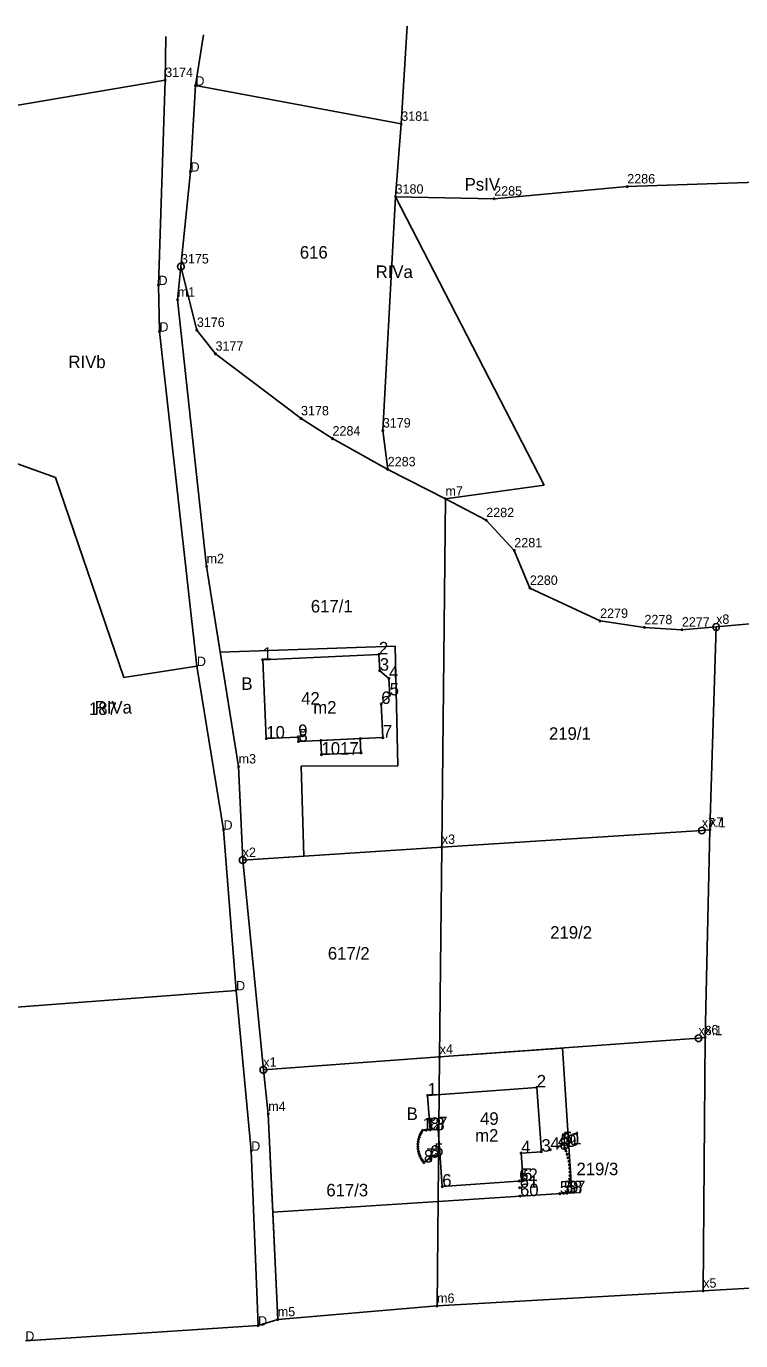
# Model space of a CAD drawing. Extents: x 7467189 to 7469366, y 5491487 to 5492734.
# Drawn here: x 7468649.2 to 7468735, y 5491668.5 to 5491826.2 of the extents above; entities that cross this region are included whole.
import ezdxf

# ---------------------------------------------------------------- set-up
doc = ezdxf.new("R2010")
doc.units = 0
for name, color, linetype in [('202-punkt graniczny', 7, 'Continuous'), ('202-punkt graniczny-Atr103', 7, 'Continuous'), ('203-punkt graniczny', 7, 'Continuous'), ('203-punkt graniczny-Atr103', 7, 'Continuous'), ('209-oznaczenie konturu klasyfikacyjnego', 7, 'Continuous'), ('210-oznaczenie konturu użytku gruntowego', 7, 'Continuous'), ('211-numer działki ewidencyjnej', 7, 'Continuous'), ('217-kontur klasyfikacyjny', 7, 'Continuous'), ('218-kontur użytku gruntowego', 7, 'Continuous'), ('219-działka ewidencyjna', 7, 'Continuous'), ('312-budynek ewidencyjny', 7, 'Continuous'), ('312-oznaczenie budynku ewidencyjnego', 7, 'Continuous'), ('312-oznaczenie budynku ewidencyjnego-Atr117', 7, 'Continuous'), ('352-schody', 7, 'Continuous'), ('Punkt budynku', 7, 'Continuous'), ('Punkt budynku-Atr104', 7, 'Continuous')]:
    doc.layers.add(name, color=color, linetype=linetype)

# ---------------------------------------------------------------- blocks, each defined once
blk = doc.blocks.new('203')
blk.add_circle((0, 0), 0.09)
blk = doc.blocks.new('202')
blk.add_circle((0, 0), 0.4)
blk = doc.blocks.new('PUNKTBUD')
blk.add_circle((0, 0), 0.09)

msp = doc.modelspace()

# ---------------------------------------------------------------- linework, layer by layer
at = {"layer": '217-kontur klasyfikacyjny'}
for points in [[(7468665.89, 5491819.71), (7468665.98, 5491824.92)], [(7468670.5, 5491825.12), (7468669.52, 5491819.04)], [(7468665.89, 5491819.71), (7468639.02, 5491815.12)], [(7468665.09, 5491795.12), (7468665.89, 5491819.71)], [(7468669.52, 5491819.04), (7468668.93, 5491808.73)], [(7468694.22, 5491814.44), (7468669.52, 5491819.04)], [(7468693.54, 5491805.71), (7468694.22, 5491814.44)], [(7468668.93, 5491808.73), (7468667.78, 5491797.33)], [(7468721.34, 5491806.93), (7468741.79, 5491807.63)], [(7468705.38, 5491805.47), (7468721.34, 5491806.93)], [(7468711.38, 5491771.14), (7468693.54, 5491805.71)], [(7468693.54, 5491805.71), (7468705.38, 5491805.47)], [(7468667.78, 5491797.33), (7468667.38, 5491793.36)], [(7468667.78, 5491797.33), (7468669.69, 5491789.73)], [(7468665.2, 5491789.55), (7468665.09, 5491795.12)], [(7468667.38, 5491793.36), (7468670.86, 5491761.39)], [(7468669.7, 5491749.44), (7468665.2, 5491789.55)], [(7468669.69, 5491789.73), (7468671.93, 5491786.88)], [(7468671.93, 5491786.88), (7468682.19, 5491779.12)], [(7468682.19, 5491779.12), (7468685.97, 5491776.71)], [(7468652.73, 5491772.06), (7468638.46, 5491777.15)], [(7468685.97, 5491776.71), (7468692.6, 5491773.01)], [(7468692.6, 5491773.01), (7468699.53, 5491769.49)], [(7468660.93, 5491748.06), (7468652.73, 5491772.06)], [(7468699.53, 5491769.49), (7468711.38, 5491771.14)], [(7468699.53, 5491769.49), (7468704.42, 5491766.92)], [(7468704.42, 5491766.92), (7468707.79, 5491763.3)], [(7468707.79, 5491763.3), (7468709.66, 5491758.79)], [(7468670.86, 5491761.39), (7468672.5, 5491751.11)], [(7468709.66, 5491758.79), (7468718.09, 5491754.84)], [(7468718.09, 5491754.84), (7468723.41, 5491754.07)], [(7468723.41, 5491754.07), (7468727.9, 5491753.79)], [(7468727.9, 5491753.79), (7468732.01, 5491754.12)], [(7468732.01, 5491754.12), (7468737.87, 5491754.64)], [(7468672.5, 5491751.11), (7468693.48, 5491751.8)], [(7468693.48, 5491751.8), (7468693.83, 5491737.45)], [(7468669.7, 5491749.44), (7468660.93, 5491748.06)], [(7468672.9, 5491729.81), (7468669.7, 5491749.44)], [(7468693.83, 5491737.45), (7468682.22, 5491737.44)], [(7468682.22, 5491737.44), (7468682.52, 5491726.65)], [(7468674.4, 5491710.54), (7468672.9, 5491729.81)], [(7468682.52, 5491726.65), (7468675.19, 5491726.17)], [(7468675.19, 5491726.17), (7468677.67, 5491701)], [(7468645.39, 5491708.33), (7468674.4, 5491710.54)], [(7468676.22, 5491691.31), (7468674.4, 5491710.54)], [(7468698.83, 5491702.56), (7468713.57, 5491703.62)], [(7468713.57, 5491703.62), (7468714.69, 5491686.26)], [(7468677.67, 5491701), (7468698.83, 5491702.56)], [(7468677.04, 5491670.34), (7468676.22, 5491691.31)], [(7468714.69, 5491686.26), (7468698.65, 5491685.23)], [(7468698.65, 5491685.23), (7468678.8, 5491683.96)], [(7468678.8, 5491683.96), (7468679.4, 5491671.07)], [(7468730.46, 5491674.51), (7468769.6, 5491676.74)], [(7468698.52, 5491672.7), (7468730.46, 5491674.51)], [(7468679.4, 5491671.07), (7468698.52, 5491672.7)], [(7468649.11, 5491668.53), (7468677.04, 5491670.34)]]:
    msp.add_lwpolyline(points, dxfattribs=at)
at = {"layer": '218-kontur użytku gruntowego'}
for points in [[(7468665.98, 5491824.92), (7468665.89, 5491819.71)], [(7468670.5, 5491825.12), (7468669.52, 5491819.04)], [(7468665.89, 5491819.71), (7468665.09, 5491795.12)], [(7468669.52, 5491819.04), (7468668.93, 5491808.73)], [(7468694.22, 5491814.44), (7468669.52, 5491819.04)], [(7468693.54, 5491805.71), (7468694.22, 5491814.44)], [(7468668.93, 5491808.73), (7468667.78, 5491797.33)], [(7468741.79, 5491807.63), (7468721.34, 5491806.93)], [(7468721.34, 5491806.93), (7468705.38, 5491805.47)], [(7468705.38, 5491805.47), (7468693.54, 5491805.71)], [(7468667.78, 5491797.33), (7468667.38, 5491793.36)], [(7468665.09, 5491795.12), (7468665.2, 5491789.55)], [(7468667.38, 5491793.36), (7468670.86, 5491761.39)], [(7468665.2, 5491789.55), (7468669.7, 5491749.44)], [(7468670.86, 5491761.39), (7468672.5, 5491751.11)], [(7468693.48, 5491751.8), (7468672.5, 5491751.11)], [(7468672.5, 5491751.11), (7468674.7, 5491737.38)], [(7468693.83, 5491737.45), (7468693.48, 5491751.8)], [(7468669.7, 5491749.44), (7468672.9, 5491729.81)], [(7468674.7, 5491737.38), (7468675.19, 5491726.17)], [(7468682.22, 5491737.44), (7468693.83, 5491737.45)], [(7468682.52, 5491726.65), (7468682.22, 5491737.44)], [(7468672.9, 5491729.81), (7468674.4, 5491710.54)], [(7468675.19, 5491726.17), (7468682.52, 5491726.65)], [(7468675.19, 5491726.17), (7468677.67, 5491701)], [(7468674.4, 5491710.54), (7468676.22, 5491691.31)], [(7468713.57, 5491703.62), (7468698.83, 5491702.56)], [(7468714.69, 5491686.26), (7468713.57, 5491703.62)], [(7468698.83, 5491702.56), (7468677.67, 5491701)], [(7468677.67, 5491701), (7468678.26, 5491695.71)], [(7468678.26, 5491695.71), (7468678.8, 5491683.96)], [(7468676.22, 5491691.31), (7468677.04, 5491670.34)], [(7468698.65, 5491685.23), (7468714.69, 5491686.26)], [(7468678.8, 5491683.96), (7468698.65, 5491685.23)], [(7468678.8, 5491683.96), (7468679.4, 5491671.07)], [(7468730.46, 5491674.51), (7468769.6, 5491676.74)], [(7468698.52, 5491672.7), (7468730.46, 5491674.51)], [(7468679.4, 5491671.07), (7468698.52, 5491672.7)], [(7468677.04, 5491670.34), (7468649.11, 5491668.53)]]:
    msp.add_lwpolyline(points, dxfattribs=at)
at = {"layer": '219-działka ewidencyjna'}
for points in [[(7468665.98, 5491824.92), (7468665.89, 5491819.71)], [(7468669.52, 5491819.04), (7468670.5, 5491825.12)], [(7468694.22, 5491814.44), (7468694.94, 5491826.16)], [(7468639.02, 5491815.12), (7468665.89, 5491819.71)], [(7468665.09, 5491795.12), (7468665.89, 5491819.71)], [(7468668.93, 5491808.73), (7468669.52, 5491819.04)], [(7468669.52, 5491819.04), (7468694.22, 5491814.44)], [(7468693.54, 5491805.71), (7468694.22, 5491814.44)], [(7468668.93, 5491808.73), (7468667.78, 5491797.33)], [(7468721.34, 5491806.93), (7468741.79, 5491807.63)], [(7468705.38, 5491805.47), (7468721.34, 5491806.93)], [(7468692.01, 5491777.67), (7468693.54, 5491805.71)], [(7468693.54, 5491805.71), (7468705.38, 5491805.47)], [(7468667.38, 5491793.36), (7468667.78, 5491797.33)], [(7468667.78, 5491797.33), (7468669.69, 5491789.73)], [(7468665.09, 5491795.12), (7468665.2, 5491789.55)], [(7468667.38, 5491793.36), (7468670.86, 5491761.39)], [(7468665.2, 5491789.55), (7468669.7, 5491749.44)], [(7468669.69, 5491789.73), (7468671.93, 5491786.88)], [(7468671.93, 5491786.88), (7468682.19, 5491779.12)], [(7468682.19, 5491779.12), (7468685.97, 5491776.71)], [(7468692.01, 5491777.67), (7468692.6, 5491773.01)], [(7468685.97, 5491776.71), (7468692.6, 5491773.01)], [(7468699.53, 5491769.49), (7468692.6, 5491773.01)], [(7468699.09, 5491727.73), (7468699.53, 5491769.49)], [(7468699.53, 5491769.49), (7468704.42, 5491766.92)], [(7468704.42, 5491766.92), (7468707.79, 5491763.3)], [(7468707.79, 5491763.3), (7468709.66, 5491758.79)], [(7468670.86, 5491761.39), (7468674.7, 5491737.38)], [(7468709.66, 5491758.79), (7468718.09, 5491754.84)], [(7468718.09, 5491754.84), (7468723.41, 5491754.07)], [(7468723.41, 5491754.07), (7468727.9, 5491753.79)], [(7468732.01, 5491754.12), (7468727.9, 5491753.79)], [(7468731.27, 5491729.81), (7468732.01, 5491754.12)], [(7468732.01, 5491754.12), (7468737.87, 5491754.64)], [(7468669.7, 5491749.44), (7468672.9, 5491729.81)], [(7468674.7, 5491737.38), (7468675.19, 5491726.17)], [(7468672.9, 5491729.81), (7468674.4, 5491710.54)], [(7468699.09, 5491727.73), (7468730.3, 5491729.72)], [(7468730.3, 5491729.72), (7468731.27, 5491729.81)], [(7468730.69, 5491704.89), (7468731.27, 5491729.81)], [(7468675.19, 5491726.17), (7468699.09, 5491727.73)], [(7468698.83, 5491702.56), (7468699.09, 5491727.73)], [(7468675.19, 5491726.17), (7468677.67, 5491701)], [(7468674.4, 5491710.54), (7468676.22, 5491691.31)], [(7468698.83, 5491702.56), (7468729.89, 5491704.8)], [(7468729.89, 5491704.8), (7468730.69, 5491704.89)], [(7468730.46, 5491674.51), (7468730.69, 5491704.89)], [(7468677.67, 5491701), (7468698.83, 5491702.56)], [(7468698.52, 5491672.7), (7468698.83, 5491702.56)], [(7468677.67, 5491701), (7468678.26, 5491695.71)], [(7468678.26, 5491695.71), (7468679.4, 5491671.07)], [(7468676.22, 5491691.31), (7468677.04, 5491670.34)], [(7468730.46, 5491674.51), (7468769.6, 5491676.74)], [(7468698.52, 5491672.7), (7468730.46, 5491674.51)], [(7468679.4, 5491671.07), (7468698.52, 5491672.7)], [(7468677.04, 5491670.34), (7468679.4, 5491671.07)], [(7468649.11, 5491668.53), (7468677.04, 5491670.34)]]:
    msp.add_lwpolyline(points, dxfattribs=at)
at = {"layer": '312-budynek ewidencyjny'}
for points in [[(7468677.59, 5491750.19), (7468691.54, 5491750.83)], [(7468691.54, 5491750.83), (7468691.64, 5491748.88)], [(7468678.02, 5491740.74), (7468677.59, 5491750.19)], [(7468691.64, 5491748.88), (7468692.75, 5491747.95)], [(7468692.75, 5491747.95), (7468692.84, 5491745.92)], [(7468692.84, 5491745.92), (7468691.82, 5491744.89)], [(7468691.82, 5491744.89), (7468692.01, 5491740.85)], [(7468681.85, 5491740.92), (7468678.02, 5491740.74)], [(7468681.88, 5491740.39), (7468681.85, 5491740.92)], [(7468692.01, 5491740.85), (7468681.88, 5491740.39)], [(7468697.38, 5491697.94), (7468710.48, 5491698.9)], [(7468710.48, 5491698.9), (7468711.04, 5491691.2)], [(7468697.68, 5491693.82), (7468697.38, 5491697.94)], [(7468698.64, 5491693.88), (7468697.68, 5491693.82)], [(7468699.14, 5491687.01), (7468698.64, 5491693.88)], [(7468711.04, 5491691.2), (7468708.61, 5491691.02)], [(7468708.61, 5491691.02), (7468708.85, 5491687.72)], [(7468708.85, 5491687.72), (7468699.14, 5491687.01)]]:
    msp.add_lwpolyline(points, dxfattribs=at)
at = {"layer": '352-schody'}
for points in [[(7468689.31, 5491740.73), (7468689.39, 5491739.03), (7468684.65, 5491738.81), (7468684.57, 5491740.51)], [(7468689.31, 5491740.73), (7468689.39, 5491739.03), (7468684.65, 5491738.81), (7468684.57, 5491740.51)], [(7468697.68, 5491693.82), (7468698.64, 5491693.88), (7468698.86, 5491690.79), (7468698.18, 5491690.7), (7468697.67, 5491690.47), (7468697.22, 5491690.11), (7468696.93, 5491689.9), (7468696.76, 5491690.14), (7468696.6, 5491690.39), (7468696.48, 5491690.66), (7468696.37, 5491690.93), (7468696.29, 5491691.22), (7468696.24, 5491691.51), (7468696.22, 5491691.8), (7468696.22, 5491692.1), (7468696.25, 5491692.39), (7468696.3, 5491692.68), (7468696.39, 5491692.96), (7468696.49, 5491693.24), (7468696.63, 5491693.5), (7468696.78, 5491693.75), (7468697.2, 5491693.78)], [(7468697.68, 5491693.82), (7468698.64, 5491693.88), (7468698.86, 5491690.79), (7468698.18, 5491690.7), (7468697.67, 5491690.47), (7468697.22, 5491690.11), (7468696.93, 5491689.9), (7468696.76, 5491690.14), (7468696.6, 5491690.39), (7468696.48, 5491690.66), (7468696.37, 5491690.93), (7468696.29, 5491691.22), (7468696.24, 5491691.51), (7468696.22, 5491691.8), (7468696.22, 5491692.1), (7468696.25, 5491692.39), (7468696.3, 5491692.68), (7468696.39, 5491692.96), (7468696.49, 5491693.24), (7468696.63, 5491693.5), (7468696.78, 5491693.75), (7468697.2, 5491693.78)]]:
    msp.add_lwpolyline(points, close=True, dxfattribs=at)

# ---------------------------------------------------------------- block references
at = {"layer": '202-punkt graniczny'}
for p in [(7468667.78, 5491797.33), (7468732.01, 5491754.12), (7468730.3, 5491729.72), (7468675.19, 5491726.17), (7468729.89, 5491704.8), (7468677.67, 5491701)]:
    msp.add_blockref('202', p, dxfattribs=at)
at = {"layer": '203-punkt graniczny'}
for p in [(7468665.89, 5491819.71), (7468669.52, 5491819.04), (7468694.22, 5491814.44), (7468668.93, 5491808.73), (7468721.34, 5491806.93), (7468693.54, 5491805.71), (7468705.38, 5491805.47), (7468665.09, 5491795.12), (7468667.38, 5491793.36), (7468665.2, 5491789.55), (7468669.69, 5491789.73), (7468671.93, 5491786.88), (7468682.19, 5491779.12), (7468692.01, 5491777.67), (7468685.97, 5491776.71), (7468692.6, 5491773.01), (7468699.53, 5491769.49), (7468704.42, 5491766.92), (7468707.79, 5491763.3), (7468670.86, 5491761.39), (7468709.66, 5491758.79), (7468718.09, 5491754.84), (7468723.41, 5491754.07), (7468727.9, 5491753.79), (7468669.7, 5491749.44), (7468674.7, 5491737.38), (7468672.9, 5491729.81), (7468731.27, 5491729.81), (7468699.09, 5491727.73), (7468674.4, 5491710.54), (7468730.69, 5491704.89), (7468698.83, 5491702.56), (7468678.26, 5491695.71), (7468676.22, 5491691.31), (7468730.46, 5491674.51), (7468698.52, 5491672.7), (7468677.04, 5491670.34), (7468679.4, 5491671.07)]:
    msp.add_blockref('203', p, dxfattribs=at)
at = {"layer": 'Punkt budynku'}
for p in [(7468691.54, 5491750.83), (7468677.59, 5491750.19), (7468691.64, 5491748.88), (7468692.75, 5491747.95), (7468691.82, 5491744.89), (7468692.84, 5491745.92), (7468678.02, 5491740.74), (7468681.85, 5491740.92), (7468681.88, 5491740.39), (7468684.57, 5491740.51), (7468689.31, 5491740.73), (7468692.01, 5491740.85), (7468684.65, 5491738.81), (7468689.39, 5491739.03), (7468710.48, 5491698.9), (7468697.38, 5491697.94), (7468696.25, 5491692.39), (7468696.3, 5491692.68), (7468696.39, 5491692.96), (7468696.49, 5491693.24), (7468696.63, 5491693.5), (7468696.78, 5491693.75), (7468697.2, 5491693.78), (7468697.68, 5491693.82), (7468698.64, 5491693.88), (7468696.22, 5491692.1), (7468696.22, 5491691.8), (7468696.24, 5491691.51), (7468696.29, 5491691.22), (7468696.37, 5491690.93), (7468708.61, 5491691.02), (7468711.04, 5491691.2), (7468712.12, 5491691.43), (7468713.01, 5491691.77), (7468713.34, 5491691.91), (7468713.64, 5491692.08), (7468713.82, 5491691.69), (7468713.99, 5491691.29), (7468714.13, 5491690.88), (7468696.48, 5491690.66), (7468696.6, 5491690.39), (7468696.76, 5491690.14), (7468696.93, 5491689.9), (7468697.22, 5491690.11), (7468697.67, 5491690.47), (7468698.18, 5491690.7), (7468698.86, 5491690.79), (7468714.24, 5491690.47), (7468714.34, 5491690.05), (7468714.41, 5491689.62), (7468708.38, 5491687.68), (7468708.85, 5491687.72), (7468714.44, 5491687.9), (7468714.45, 5491689.2), (7468714.47, 5491688.77), (7468714.47, 5491688.33), (7468699.14, 5491687.01), (7468708.43, 5491686.87), (7468713.25, 5491686.17), (7468713.72, 5491686.21), (7468714.09, 5491686.22), (7468714.21, 5491686.63), (7468714.31, 5491687.05), (7468714.39, 5491687.48), (7468708.47, 5491685.87)]:
    msp.add_blockref('PUNKTBUD', p, dxfattribs=at)

# ---------------------------------------------------------------- texts
at = {"layer": '202-punkt graniczny-Atr103'}
for s, p in [('3175', (7468667.78, 5491797.71)), ('x8', (7468732.01, 5491754.5)), ('x7.1', (7468730.3, 5491730.1)), ('x2', (7468675.19, 5491726.54)), ('x6.1', (7468729.89, 5491705.17)), ('x1', (7468677.67, 5491701.38))]:
    msp.add_text(s, height=1.125, dxfattribs=at).set_placement(p)
at = {"layer": '203-punkt graniczny-Atr103'}
for s, height, p in [('3174', 1.125, (7468665.89, 5491820.08)), ('D', 1.12, (7468669.52, 5491819.04)), ('3181', 1.125, (7468694.22, 5491814.82)), ('D', 1.12, (7468668.93, 5491808.73)), ('2286', 1.125, (7468721.34, 5491807.31)), ('3180', 1.125, (7468693.54, 5491806.08)), ('2285', 1.125, (7468705.38, 5491805.85)), ('D', 1.12, (7468665.09, 5491795.12)), ('m1', 1.125, (7468667.38, 5491793.74)), ('D', 1.12, (7468665.2, 5491789.55)), ('3176', 1.125, (7468669.69, 5491790.11)), ('3177', 1.125, (7468671.93, 5491787.25)), ('3178', 1.125, (7468682.19, 5491779.5)), ('3179', 1.125, (7468692.01, 5491778.04)), ('2284', 1.125, (7468685.97, 5491777.08)), ('2283', 1.125, (7468692.6, 5491773.39)), ('m7', 1.125, (7468699.53, 5491769.87)), ('2282', 1.125, (7468704.42, 5491767.29)), ('2281', 1.125, (7468707.79, 5491763.67)), ('m2', 1.125, (7468670.86, 5491761.77)), ('2280', 1.125, (7468709.66, 5491759.17)), ('2279', 1.125, (7468718.09, 5491755.21)), ('2278', 1.125, (7468723.41, 5491754.45)), ('2277', 1.125, (7468727.9, 5491754.17)), ('D', 1.12, (7468669.7, 5491749.44)), ('m3', 1.125, (7468674.7, 5491737.75)), ('D', 1.12, (7468672.9, 5491729.81)), ('x7', 1.125, (7468731.27, 5491730.18)), ('x3', 1.125, (7468699.09, 5491728.11)), ('D', 1.12, (7468674.4, 5491710.54)), ('x6', 1.125, (7468730.69, 5491705.27)), ('x4', 1.125, (7468698.83, 5491702.93)), ('m4', 1.125, (7468678.26, 5491696.08)), ('D', 1.12, (7468676.22, 5491691.31)), ('x5', 1.125, (7468730.46, 5491674.89)), ('m6', 1.125, (7468698.52, 5491673.08)), ('m5', 1.125, (7468679.4, 5491671.45)), ('D', 1.12, (7468677.04, 5491670.34)), ('D', 1.12, (7468649.11, 5491668.53))]:
    msp.add_text(s, height=height, dxfattribs=at).set_placement(p)
at = {"layer": '209-oznaczenie konturu klasyfikacyjnego'}
for s, p in [('PsIV', (7468701.83, 5491806.46)), ('RIVa', (7468691.15, 5491795.97)), ('RIVb', (7468654.28, 5491785.17)), ('RIVa', (7468657.43, 5491743.74))]:
    msp.add_text(s, height=1.5, dxfattribs=at).set_placement(p)
at = {"layer": '210-oznaczenie konturu użytku gruntowego'}
for s, p in [('Ps', (7468701.83, 5491806.46)), ('B', (7468675.04, 5491746.58)), ('B', (7468694.87, 5491695))]:
    msp.add_text(s, height=1.5, dxfattribs=at).set_placement(p)
at = {"layer": '211-numer działki ewidencyjnej'}
for s, p in [('616', (7468682.05, 5491798.3)), ('617/1', (7468683.37, 5491755.86)), ('187', (7468656.74, 5491743.58)), ('219/1', (7468711.95, 5491740.59)), ('219/2', (7468712.1, 5491716.74)), ('617/2', (7468685.41, 5491714.23)), ('219/3', (7468715.25, 5491688.38)), ('617/3', (7468685.23, 5491685.84))]:
    msp.add_text(s, height=1.5, dxfattribs=at).set_placement(p)
at = {"layer": '312-oznaczenie budynku ewidencyjnego'}
for s, p in [('42', (7468682.21, 5491744.81)), ('49', (7468703.68, 5491694.42))]:
    msp.add_text(s, height=1.5, dxfattribs=at).set_placement(p)
at = {"layer": '312-oznaczenie budynku ewidencyjnego-Atr117'}
for p in [(7468683.66, 5491743.73), (7468703.09, 5491692.4)]:
    msp.add_text('m2', height=1.5, dxfattribs=at).set_placement(p)
at = {"layer": 'Punkt budynku-Atr104'}
for s, p in [('1', (7468677.59, 5491750.19)), ('2', (7468691.54, 5491750.83)), ('3', (7468691.64, 5491748.88)), ('4', (7468692.75, 5491747.95)), ('6', (7468691.82, 5491744.89)), ('5', (7468692.84, 5491745.92)), ('10', (7468678.02, 5491740.74)), ('9', (7468681.85, 5491740.92)), ('8', (7468681.88, 5491740.39)), ('7', (7468692.01, 5491740.85)), ('1017', (7468684.65, 5491738.81)), ('2', (7468710.48, 5491698.9)), ('1', (7468697.38, 5491697.94)), ('12', (7468696.78, 5491693.75)), ('13', (7468697.2, 5491693.78)), ('8', (7468697.68, 5491693.82)), ('7', (7468698.64, 5491693.88)), ('4', (7468708.61, 5491691.02)), ('3', (7468711.04, 5491691.2)), ('48', (7468712.12, 5491691.43)), ('49', (7468713.01, 5491691.77)), ('50', (7468713.34, 5491691.91)), ('51', (7468713.64, 5491692.08)), ('8', (7468696.93, 5491689.9)), ('7', (7468697.22, 5491690.11)), ('6', (7468697.67, 5491690.47)), ('5', (7468698.18, 5491690.7)), ('6', (7468699.14, 5491687.01)), ('62', (7468708.38, 5491687.68)), ('61', (7468708.43, 5491686.87)), ('5', (7468708.85, 5491687.72)), ('60', (7468708.47, 5491685.87)), ('59', (7468713.25, 5491686.17)), ('58', (7468713.72, 5491686.21)), ('57', (7468714.09, 5491686.22))]:
    msp.add_text(s, height=1.5, dxfattribs=at).set_placement(p)

doc.saveas('drawing.dxf')
